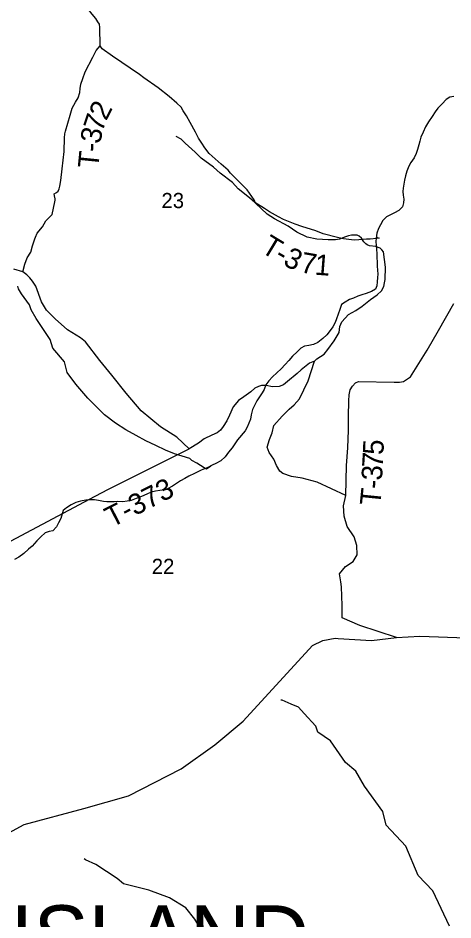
# Model space of a CAD drawing. Extents: x 0 to 34, y 0 to 22.
# Drawn here: x 6.741 to 7.939, y 18.266 to 20.751 of the extents above; entities that cross this region are included whole.
import ezdxf

# ---------------------------------------------------------------- set-up
doc = ezdxf.new("R2010")
doc.units = 0
for name, color, linetype in [('GM_X_County_Road', 7, 'Continuous'), ('GM_X_Minor_River', 7, 'Continuous'), ('GM_X_Section_Text', 7, 'Continuous'), ('GM_X_Township_Road', 7, 'Continuous'), ('GM_X_Township_Road_Text', 7, 'Continuous'), ('GM_X_Township_Text', 7, 'Continuous')]:
    doc.layers.add(name, color=color, linetype=linetype)

msp = doc.modelspace()

# ---------------------------------------------------------------- linework, layer by layer
at = {"layer": 'GM_X_County_Road'}
for points in [[(6.2654, 18.3708), (6.3464, 18.3757), (6.6287, 18.4593), (6.7574, 18.5293), (6.9222, 18.5733), (7.0449, 18.6084), (7.1902, 18.6821), (7.2829, 18.7485), (7.3608, 18.8138), (7.5525, 19.022), (7.5804, 19.0364), (7.6144, 19.0421), (7.6225, 19.0416)], [(7.6225, 19.0416), (7.715, 19.0364), (7.7831, 19.0443), (7.8475, 19.048), (7.9757, 19.0435)]]:
    msp.add_lwpolyline(points, dxfattribs=at)
at = {"layer": 'GM_X_Minor_River'}
for points in [[(7.9413, 20.5348), (7.9303, 20.533), (7.9203, 20.5262), (7.9088, 20.5148), (7.8974, 20.5023), (7.8898, 20.4925), (7.8814, 20.4801), (7.8716, 20.4649), (7.8633, 20.451), (7.8565, 20.4367), (7.8509, 20.4228), (7.8474, 20.412), (7.845, 20.402), (7.8413, 20.389), (7.8374, 20.3778), (7.8317, 20.3659), (7.8233, 20.3534), (7.8172, 20.3429), (7.8123, 20.3287), (7.8081, 20.3164), (7.8051, 20.3041), (7.8035, 20.2934), (7.802, 20.2827), (7.8011, 20.2732), (7.8018, 20.2629), (7.8033, 20.2523), (7.8028, 20.242), (7.8001, 20.2309), (7.7902, 20.2207), (7.7782, 20.2146), (7.7685, 20.2101), (7.7561, 20.2029), (7.7454, 20.193), (7.7393, 20.1814), (7.7343, 20.1713), (7.729, 20.1582), (7.7271, 20.1445), (7.7267, 20.1349), (7.727, 20.1243), (7.7281, 20.1137), (7.7292, 20.1023), (7.7295, 20.0909), (7.7303, 20.0787), (7.7306, 20.0673), (7.7314, 20.0563), (7.7317, 20.0453), (7.7312, 20.0357), (7.7305, 20.0243), (7.7296, 20.0132), (7.7258, 20.0036)], [(7.7275, 20.1471), (7.7354, 20.1447), (7.7283, 20.1434), (7.7105, 20.142), (7.7007, 20.1418), (7.6799, 20.14), (7.6671, 20.139), (7.6379, 20.1423), (7.6205, 20.1462), (7.5814, 20.1566), (7.5612, 20.1643), (7.5228, 20.1766), (7.5046, 20.1835), (7.4722, 20.1955), (7.4585, 20.2037), (7.4333, 20.2173), (7.4203, 20.2262), (7.3932, 20.2429), (7.3786, 20.256), (7.3475, 20.2806), (7.3314, 20.2975), (7.2973, 20.3235), (7.2792, 20.34), (7.2451, 20.3649), (7.2286, 20.381), (7.2013, 20.406), (7.1906, 20.4176), (7.1764, 20.4246)], [(7.7258, 20.0036), (7.7142, 19.9979), (7.6999, 19.9925), (7.6878, 19.9887), (7.6765, 19.9849), (7.6653, 19.9796), (7.6544, 19.9755), (7.6421, 19.9682), (7.6316, 19.9614), (7.6275, 19.948), (7.6184, 19.9222), (7.6142, 19.9118), (7.6081, 19.8998), (7.6011, 19.8897), (7.5916, 19.8783), (7.5805, 19.8681), (7.5664, 19.857), (7.5544, 19.8513), (7.5423, 19.8486), (7.5299, 19.8467), (7.5201, 19.8411), (7.5098, 19.8312), (7.4972, 19.8198), (7.4866, 19.8076), (7.4767, 19.7963), (7.466, 19.7845), (7.4542, 19.7731), (7.4423, 19.7621), (7.432, 19.7515), (7.4232, 19.7406), (7.4191, 19.7279), (7.4133, 19.7182), (7.4064, 19.7077), (7.3991, 19.696), (7.393, 19.6852), (7.3869, 19.6724), (7.3832, 19.6582), (7.3809, 19.6463), (7.3767, 19.6348), (7.3721, 19.6236), (7.3663, 19.6135), (7.3458, 19.5885), (7.3305, 19.5667), (7.321, 19.5546), (7.3115, 19.5417), (7.2993, 19.5311), (7.2862, 19.5238), (7.2761, 19.5189), (7.2633, 19.5128), (7.2457, 19.505), (7.227, 19.4965), (7.2112, 19.4887), (7.2008, 19.4823), (7.1884, 19.4758), (7.1772, 19.4686), (7.1661, 19.461), (7.153, 19.4542), (7.1432, 19.4508), (7.1319, 19.4489), (7.1197, 19.4474), (7.108, 19.4448), (7.0956, 19.4394), (7.081, 19.4329), (7.0664, 19.4271), (7.0525, 19.4217), (7.0419, 19.4195), (7.0294, 19.4183), (7.0161, 19.4186), (7.0058, 19.4183), (6.9955, 19.4184), (6.986, 19.4181), (6.9761, 19.4193), (6.9627, 19.4219), (6.9513, 19.4235), (6.9402, 19.4239), (6.9273, 19.4227), (6.913, 19.4196), (6.8998, 19.4161), (6.8871, 19.41), (6.8748, 19.402), (6.8651, 19.3945), (6.8586, 19.3726), (6.8525, 19.3598), (6.8467, 19.3494), (6.8368, 19.3384), (6.827, 19.3362), (6.8161, 19.3324), (6.8035, 19.3217), (6.7924, 19.3107), (6.7795, 19.2962), (6.7699, 19.2876), (6.757, 19.2757), (6.7428, 19.2654), (6.7316, 19.2589)], [(7.2717, 19.5168), (7.2599, 19.5082), (7.2541, 19.5119), (7.2331, 19.5248), (7.2198, 19.5322), (7.214, 19.5371), (7.1718, 19.5505), (7.1467, 19.5603), (7.1208, 19.5732), (7.0933, 19.5865), (7.0659, 19.6005), (7.038, 19.6164), (7.0093, 19.6345), (6.9791, 19.658), (6.9333, 19.7037), (6.9005, 19.742), (6.8761, 19.7747), (6.8692, 19.8039), (6.8364, 19.8414), (6.8296, 19.8653), (6.7912, 19.9232), (6.7772, 19.9474), (6.7724, 19.9606), (6.7503, 19.9911), (6.7426, 20.0046), (6.7402, 20.0126)], [(7.9293, 18.2487), (7.8838, 18.3465), (7.8433, 18.3888), (7.809, 18.4696), (7.7547, 18.5276), (7.7454, 18.5647), (7.6954, 18.6347), (7.6716, 18.6761), (7.6432, 18.7), (7.6017, 18.7598), (7.5669, 18.7835), (7.5609, 18.8002), (7.5293, 18.835), (7.5135, 18.8526), (7.4937, 18.8611), (7.4682, 18.872), (7.4648, 18.872)], [(7.3654, 17.9677), (7.3601, 17.9865), (7.3601, 17.9915), (7.3592, 17.9964), (7.353, 18.0263), (7.3514, 18.0545), (7.3469, 18.0707), (7.3367, 18.0926), (7.3232, 18.1296), (7.3122, 18.1553), (7.2959, 18.1771), (7.2812, 18.194), (7.2646, 18.2134), (7.2484, 18.2345), (7.2278, 18.2687), (7.2034, 18.2995), (7.1579, 18.3269), (7.1012, 18.348), (7.0317, 18.3655), (7.0137, 18.3807), (6.9548, 18.4193), (6.9266, 18.4318), (6.9232, 18.4344)]]:
    msp.add_lwpolyline(points, dxfattribs=at)
at = {"layer": 'GM_X_Township_Road'}
for points in [[(6.9673, 20.6747), (6.9661, 20.7252), (6.9651, 20.7339), (6.9609, 20.7404), (6.9549, 20.7493), (6.9452, 20.7615), (6.9352, 20.7743), (6.9302, 20.7824), (6.9271, 20.7905), (6.9263, 20.8027), (6.9251, 20.8114), (6.9236, 20.8208), (6.9214, 20.8286), (6.9193, 20.8325), (6.917, 20.8358), (6.9028, 20.8495), (6.8913, 20.863)], [(6.8559, 20.2874), (6.8586, 20.3032), (6.8623, 20.3359), (6.8678, 20.3836), (6.8691, 20.4208), (6.8699, 20.4316), (6.8721, 20.4395), (6.8849, 20.4835), (6.8902, 20.5028), (6.8995, 20.5189), (6.9069, 20.5315), (6.9113, 20.5462), (6.9118, 20.5564), (6.9138, 20.569), (6.9191, 20.5845), (6.9256, 20.6024), (6.9466, 20.6436), (6.9558, 20.6615), (6.9673, 20.6747)], [(7.0872, 20.5866), (7.0751, 20.5952), (7.0009, 20.6457), (6.9731, 20.6662), (6.9673, 20.6747)], [(7.6435, 19.436), (7.565, 19.4725), (7.5239, 19.4831), (7.4942, 19.4883), (7.4708, 19.4964), (7.4621, 19.503), (7.4525, 19.5185), (7.4457, 19.5355), (7.4328, 19.5542), (7.4275, 19.5687), (7.4336, 19.5895), (7.4407, 19.6083), (7.4451, 19.6288), (7.4682, 19.6538), (7.4874, 19.6733), (7.5016, 19.6853), (7.5166, 19.7015), (7.5397, 19.7516), (7.5574, 19.806), (7.5641, 19.8124), (7.584, 19.8247), (7.594, 19.8381), (7.6119, 19.8617), (7.6253, 19.8843), (7.6272, 19.9015), (7.6331, 19.9139), (7.6515, 19.934), (7.6716, 19.9455), (7.6886, 19.9571), (7.7121, 19.9759), (7.7302, 19.9888), (7.7421, 19.9993), (7.7484, 20.0112), (7.7508, 20.0215), (7.7522, 20.0304), (7.7534, 20.0645), (7.7472, 20.1065), (7.7429, 20.112), (7.738, 20.1165), (7.7333, 20.119), (7.7269, 20.1215), (7.7087, 20.1237), (7.7029, 20.1258), (7.699, 20.129), (7.6937, 20.1345), (7.6868, 20.1449), (7.6809, 20.1502), (7.6752, 20.1525), (7.6681, 20.1532), (7.6595, 20.1524), (7.6516, 20.151), (7.6426, 20.1479), (7.6265, 20.1416), (7.6153, 20.1396), (7.5952, 20.1396), (7.5644, 20.142), (7.537, 20.1473), (7.5087, 20.1612), (7.4847, 20.1777), (7.4473, 20.1978), (7.4268, 20.2104), (7.3955, 20.2411), (7.3913, 20.2498), (7.3725, 20.2777), (7.3262, 20.324), (7.3194, 20.3314), (7.3002, 20.3487), (7.2678, 20.3776), (7.2556, 20.3931), (7.2472, 20.4059), (7.2383, 20.4203), (7.2295, 20.4369), (7.2153, 20.4629), (7.205, 20.4813), (7.1962, 20.4952), (7.19, 20.5051), (7.1784, 20.5168), (7.1577, 20.5345), (7.1268, 20.5584), (7.0872, 20.5866)], [(6.7888, 20.147), (6.7933, 20.158), (6.8081, 20.1758), (6.8176, 20.1918), (6.8348, 20.2094), (6.839, 20.2269), (6.8425, 20.2445), (6.8435, 20.2494), (6.8432, 20.2531), (6.8416, 20.2607), (6.8406, 20.2667), (6.8472, 20.2702), (6.8514, 20.2744), (6.8547, 20.2805), (6.8559, 20.2874)], [(6.7538, 20.0515), (6.7596, 20.0733), (6.7664, 20.0899), (6.776, 20.1056), (6.7805, 20.1233), (6.7872, 20.1429), (6.7888, 20.147)], [(7.212, 19.5645), (7.1781, 19.5963), (7.133, 19.6243), (7.0805, 19.6687), (7.0392, 19.7175), (6.9993, 19.7672), (6.9667, 19.8079), (6.9266, 19.8589), (6.9126, 19.8697), (6.8771, 19.8918), (6.8431, 19.9222), (6.8195, 19.9463), (6.8052, 19.9693), (6.7903, 20.0122), (6.7809, 20.0262), (6.7739, 20.0349), (6.7648, 20.0437), (6.7538, 20.0515), (6.729, 20.0588)], [(7.6299, 19.1976), (7.6264, 19.2201), (7.6433, 19.24), (7.6639, 19.2536), (7.6752, 19.2718), (7.6746, 19.2974), (7.6666, 19.3215), (7.6479, 19.3498), (7.6394, 19.3786), (7.6378, 19.4069), (7.6435, 19.436), (7.646, 19.5184), (7.6496, 19.5672), (7.651, 19.6152), (7.6516, 19.653), (7.6522, 19.6967), (7.6535, 19.7128), (7.656, 19.7266), (7.6623, 19.7363), (7.6709, 19.7457), (7.6788, 19.7498), (7.7772, 19.7481), (7.7921, 19.7478), (7.8031, 19.7495), (7.8222, 19.7622), (7.8676, 19.8358), (7.8992, 19.8904), (7.9418, 19.9644)], [(7.5574, 19.806), (7.5442, 19.8002), (7.5209, 19.7813), (7.5094, 19.7714), (7.4834, 19.75), (7.4718, 19.7407), (7.4598, 19.7358), (7.4419, 19.7352), (7.4247, 19.7384), (7.412, 19.7384), (7.4035, 19.7361), (7.3934, 19.7308), (7.382, 19.7208), (7.3625, 19.7073), (7.3486, 19.6976), (7.3334, 19.6801), (7.3231, 19.657), (7.3165, 19.6416), (7.3056, 19.6257), (7.2983, 19.6156), (7.2896, 19.6086), (7.2749, 19.602), (7.2538, 19.5918), (7.238, 19.5797), (7.212, 19.5645)], [(6.9532, 19.4333), (6.9897, 19.4526), (7.212, 19.5645)], [(6.605, 19.2486), (6.6142, 19.2576), (6.633, 19.2641), (6.9532, 19.4333)], [(7.7831, 19.0443), (7.6825, 19.0771), (7.634, 19.0983), (7.634, 19.1324), (7.632, 19.1839), (7.6299, 19.1976)]]:
    msp.add_lwpolyline(points, dxfattribs=at)

# ---------------------------------------------------------------- texts
at = {"layer": 'GM_X_Section_Text'}
for s, p in [('23', (7.136, 20.2273)), ('22', (7.1093, 19.2193))]:
    msp.add_text(s, height=0.04186, rotation=0, dxfattribs=at).set_placement(p)
at = {"layer": 'GM_X_Township_Road_Text'}
for s, height, rotation, p in [('2', 0.0568, 62.8624, (6.9836, 20.4659)), ('7', 0.0568, 71.4976, (6.9733, 20.4348)), ('3', 0.0568, 78.6115, (6.9669, 20.4023)), ('-', 0.0568, 88.1323, (6.9664, 20.3815)), ('T', 0.0568, 84.3295, (6.9619, 20.3351)), ('T', 0.0568, 328.8782, (7.4069, 20.1079)), ('-', 0.0568, 330.0266, (7.4444, 20.0853)), ('3', 0.0568, 333.8375, (7.4682, 20.0717)), ('7', 0.0568, 350.1359, (7.5164, 20.0509)), ('1', 0.0568, 355.5926, (7.5567, 20.0441)), ('5', 0.0568, 87.2987, (7.7471, 19.5465)), ('7', 0.0568, 86.5373, (7.745, 19.5108)), ('3', 0.0568, 87.9752, (7.7438, 19.4762)), ('T-373', 0.05682, 26.9405, (6.9988, 19.3461)), ('T', 0.0568, 84.3295, (7.7387, 19.4062)), ('-', 0.0568, 88.4418, (7.7431, 19.453))]:
    msp.add_text(s, height=height, rotation=rotation, dxfattribs=at).set_placement(p)
at = {"layer": 'GM_X_Township_Text'}
msp.add_text('ISLAND', height=0.17045, rotation=0, dxfattribs=at).set_placement((6.7201, 18.1359))

doc.saveas('drawing.dxf')
